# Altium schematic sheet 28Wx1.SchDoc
size A2; SheetNumber: 0; SheetTotal: 0; PageSetup: Record=PageOptions|CenterHorizontal=True|CenterVertical=True|PrintScale=0.52|XCorrection=1.00|YCorrection=1.00|PrintKind=0|BorderSize=5000000|LeftOffset=0|BottomOffset=0|Orientation=2|PaperLength=1000|PaperWidth=1000|Scale=100|PaperSource=7|PrintQuality=-4|MediaType=1|DitherType=10|PaperKind=A4|PrintScaleMode=1
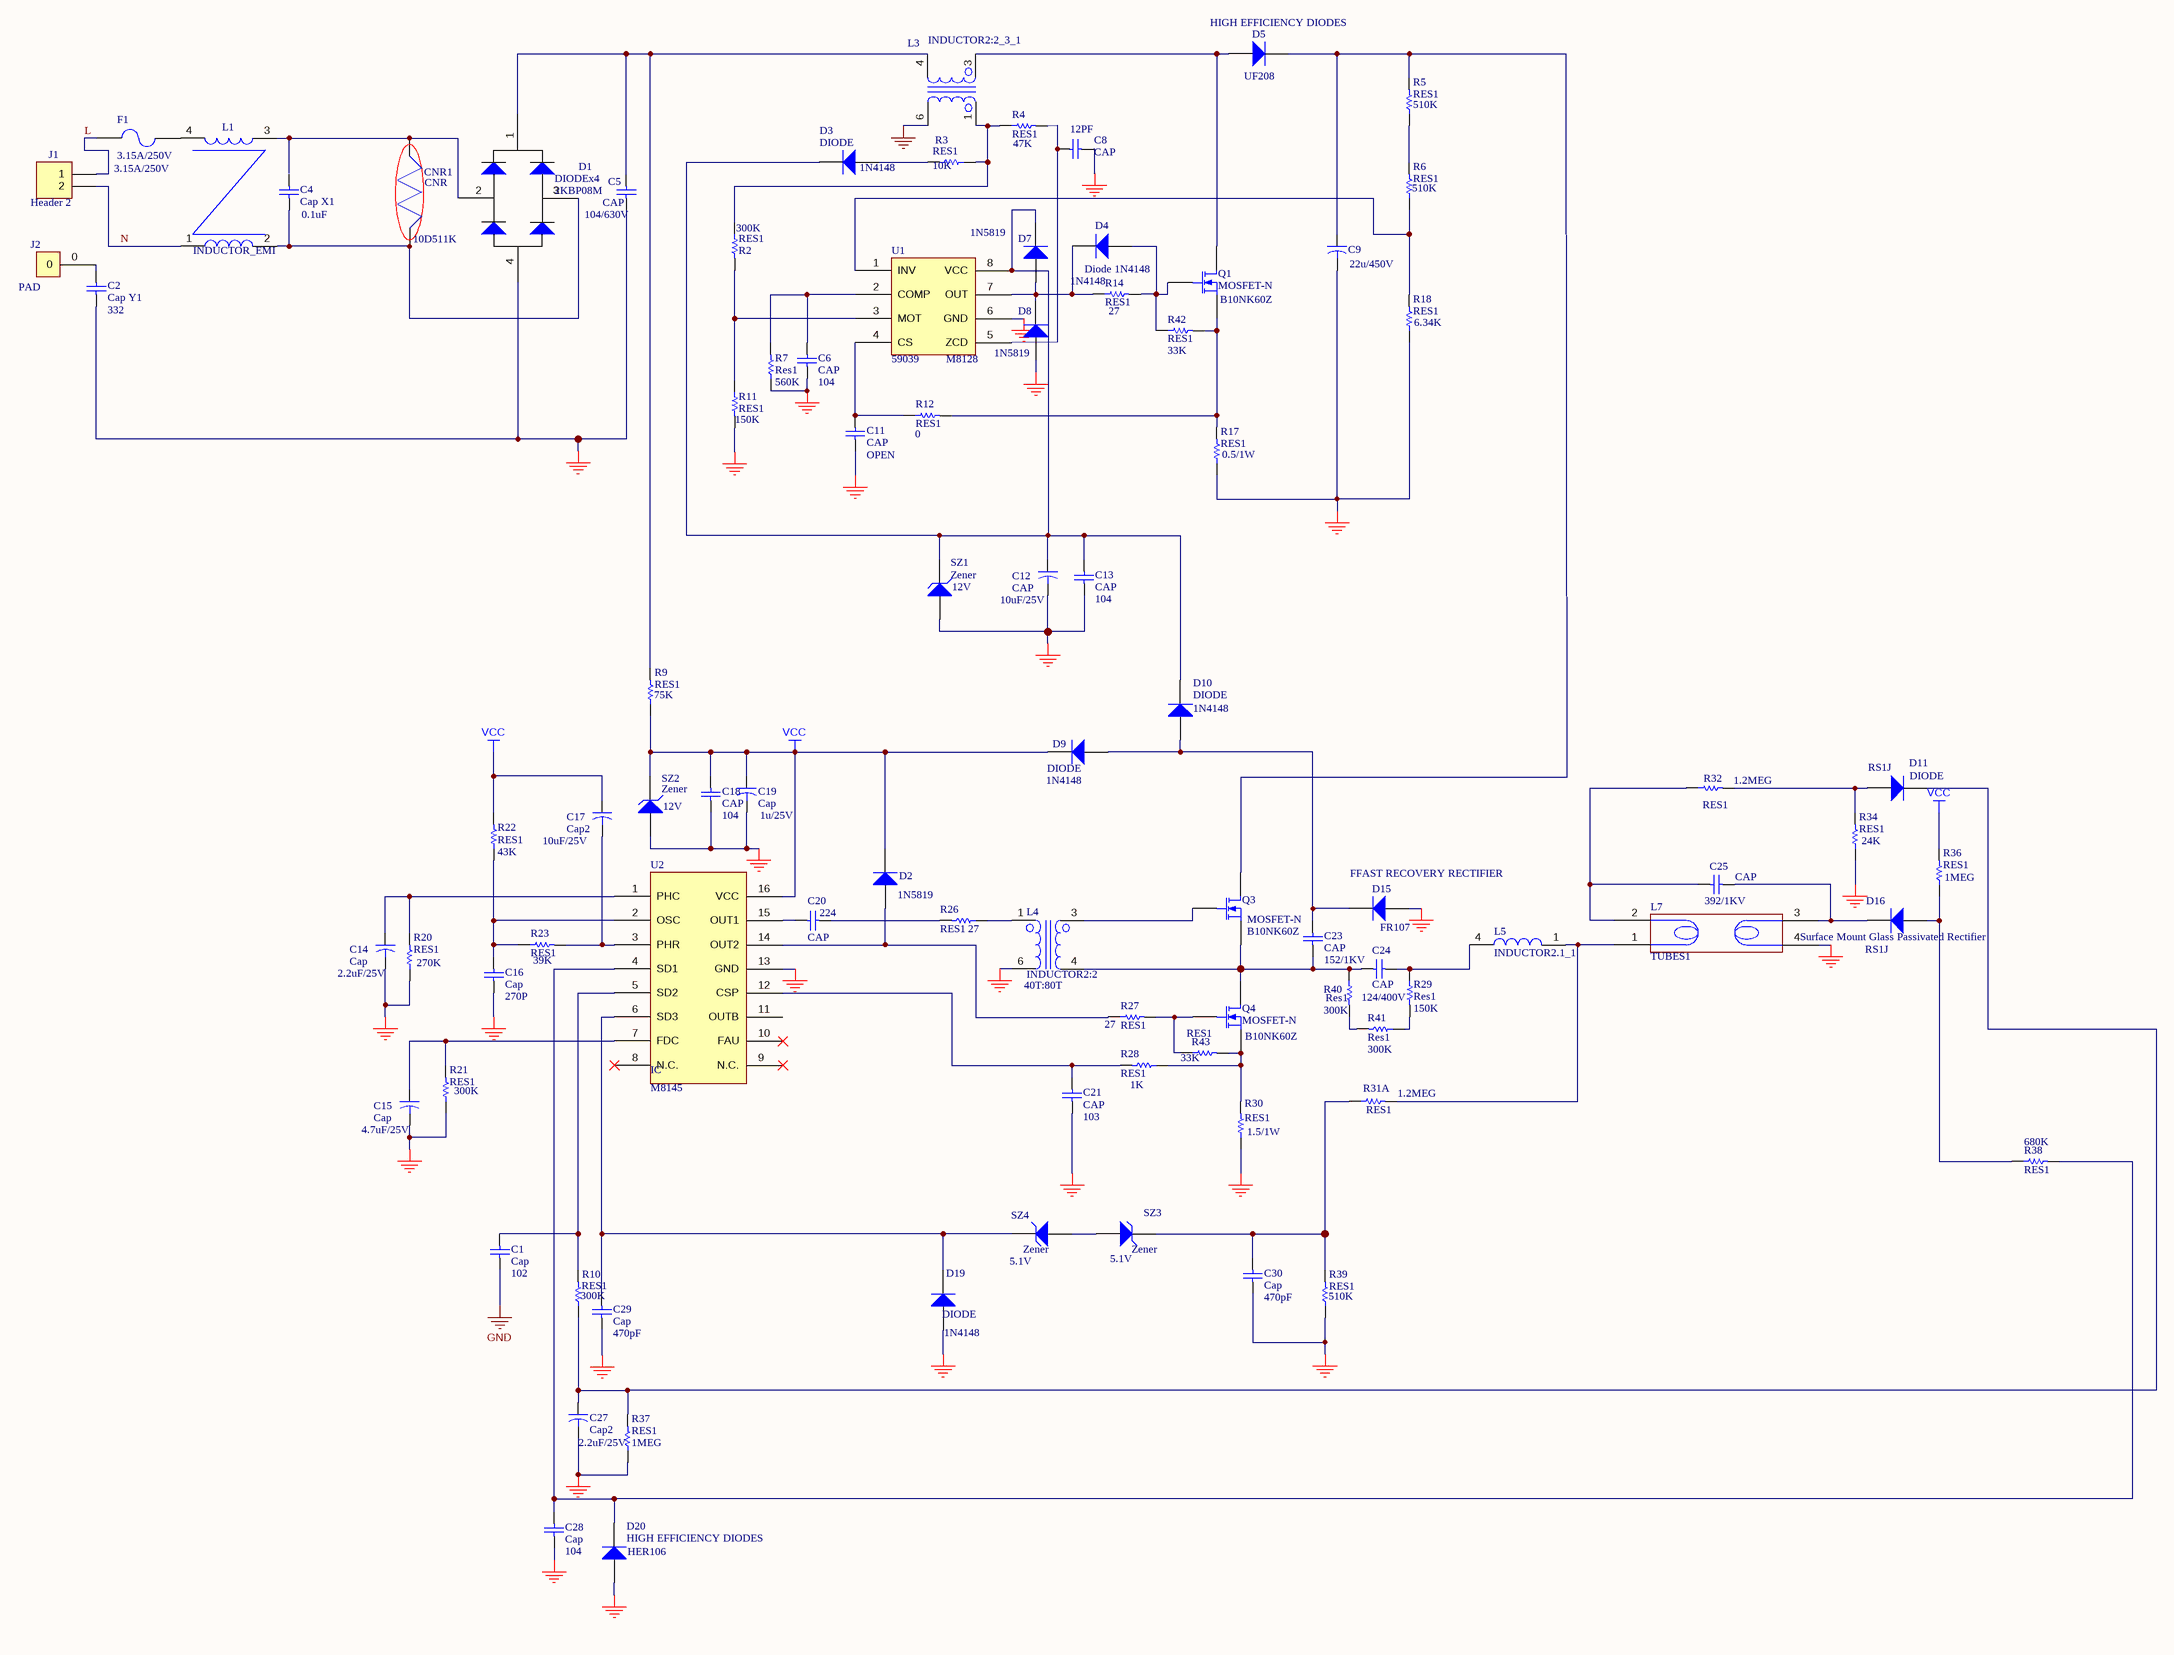
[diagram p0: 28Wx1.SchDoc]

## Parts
C1  Cap  value 102  [C0805A]
C2  Cap Y1  value 332  [RAD-0.3]
C4  Cap X1  value 0.1uF  [RAD0.6B]
C5  CAP  value 104/630V  [RAD0.6B]
C6  CAP  value 104  [RAD0.2B]
C8  CAP  value 12PF  [C0805A]
C9  value 22u/450V  [RB.3/.6A]  (hidden comment: Cap2)
C11  CAP  value OPEN  [C0805A]
C12  CAP  value 10uF/25V  [RB.2/.2]
C13  CAP  value 104  [RAD0.2B]
C14  Cap  value 2.2uF/25V  [RB.2/.2]
C15  Cap  value 4.7uF/25V  [RB.2/.2]
C16  Cap  value 270P  [C0805A]
C17  Cap2  value 10uF/25V  [RB.2/.2]
C18  CAP  value 104  [RAD0.2B]
C19  Cap  value 1u/25V  [RB.2/.2]
C20  CAP  value 224  [C0805A]
C21  CAP  value 103  [C0805A]
C23  CAP  value 152/1KV  [RAD-0.3]
C24  CAP  value 124/400V  [RAD0.6A]
C25  CAP  value 392/1KV  [RAD0.6A]
C27  Cap2  value 2.2uF/25V  [RB.2/.2]
C28  Cap  value 104  [C0805A]
C29  Cap  value 470pF  [C0805A]
C30  Cap  value 470pF  [C0805A]
CNR1  CNR  value 10D511K  [RAD-0.2]
D1  DIODEx4  value 2KBP08M  [SIP4C]
D2  value 1N5819  [DO-41]  (hidden comment: Diode 1N5819)
D3  DIODE  value 1N4148  [CD3216-1206A]
D4  Diode 1N4148  value 1N4148  [CD3216-1206A]
D5  HIGH EFFICIENCY DIODES  value UF208  [DIODE-0.4]
D7  value 1N5819  [CD4532-1812A]  (hidden comment: Diode 1N5819)
D8  value 1N5819  [CD4532-1812A]  (hidden comment: Diode 1N5819)
D9  DIODE  value 1N4148  [CD3216-1206A]
D10  DIODE  value 1N4148  [CD3216-1206A]
D11  DIODE  value RS1J  [CD4532-1810]
D15  FFAST RECOVERY RECTIFIER  value FR107  [DIODE-0.4]
D16  Surface Mount Glass Passivated Rectifier  value RS1J  [CD4532-1810]
D19  DIODE  value 1N4148  [CD3216-1206A]
D20  HIGH EFFICIENCY DIODES  value HER106  [DIODE-0.4]
F1  3.15A/250V  [FUSE0.6]
J1  Header 2  [IDC4-3.8mm]
J2  PAD  [GND1]
L1  INDUCTOR_EMI  [EE1414H]
L3  INDUCTOR2:2_3_1  [EE2520H]
L4  INDUCTOR2:2  value 40T:80T  [EE0808]
L5  INDUCTOR2.1_1  [EE2720H]
L7  TUBES1  [IDC8-3.8MM]
Q1  MOSFET-N  value B10NK60Z  [TO-220B]
Q3  MOSFET-N  value B10NK60Z  [TO-220B]
Q4  MOSFET-N  value B10NK60Z  [TO-220B]
R2  RES1  value 300K  [2012[0805]A]
R3  RES1  value 10K  [2012[0805]A]
R4  RES1  value 47K  [2012[0805]A]
R5  RES1  value 510K  [2012[0805]A]
R6  RES1  value 510K  [2012[0805]A]
R7  Res1  value 560K  [2012[0805]A]
R9  RES1  value 75K  [2012[0805]A]
R10  RES1  value 300K  [2012[0805]A]
R11  RES1  value 150K  [2012[0805]A]
R12  RES1  value 0  [2012[0805]A]
R14  RES1  value 27  [2012[0805]A]
R17  RES1  value 0.5/1W  [AXIAL-0.5]
R18  RES1  value 6.34K  [2012[0805]A]
R20  RES1  value 270K  [2012[0805]A]
R21  RES1  value 300K  [2012[0805]A]
R22  RES1  value 43K  [2012[0805]A]
R23  RES1  value 39K  [2012[0805]A]
R26  RES1  value 27  [2012[0805]A]
R27  RES1  value 27  [2012[0805]A]
R28  RES1  value 1K  [2012[0805]A]
R29  Res1  value 150K  [2012[0805]A]
R30  RES1  value 1.5/1W  [AXIAL-0.5]
R31A  RES1  value 1.2MEG  [2012[0805]A]
R32  RES1  value 1.2MEG  [2012[0805]A]
R34  RES1  value 24K  [2012[0805]A]
R36  RES1  value 1MEG  [2012[0805]A]
R37  RES1  value 1MEG  [2012[0805]A]
R38  RES1  value 680K  [2012[0805]A]
R39  RES1  value 510K  [2012[0805]A]
R40  Res1  value 300K  [2012[0805]A]
R41  Res1  value 300K  [2012[0805]A]
R42  RES1  value 33K  [2012[0805]A]
R43  RES1  value 33K  [2012[0805]A]
SZ1  Zener  value 12V  [CD3216-1206A]
SZ2  Zener  value 12V  [CD3216-1206A]
SZ3  Zener  value 5.1V  [CD3216-1206A]
SZ4  Zener  value 5.1V  [CD3216-1206A]
U1  59039  value M8128  [DIP-8]
U2  IC  value M8145  [SO-16]

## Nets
GND: C1.1 C2.1 C5.1 C6.1 C8.2 C9.2 C11.1 C12.2 C13.1 C14.2 C15.2 C16.1 C18.1 C19.2 C21.1 C27.2 C28.2 C29.1 C30.2 D1.4 D8.1(A) D15.1(A) D19.1(A) D20.1(A) L3.6 L4.6 L7.4(TR4) R7.1 R11.2 R17.1 R18.1 R20.1 R21.1 R30.1 R34.1 R37.1 R39.1 SZ1.1(A) SZ2.1(A) U1.6(GND) U2.13(GND)
VCC: C17.1 C18.2 C19.1 D2.2(K) D9.2(K) R9.1 R22.2 R36.2 SZ2.2(K) U2.16(VCC)
L: F1.1 J1.1
N: J1.2 L1.1(TR5)
NetC1_2: C1.2 R10.2 U2.5(SD2)
NetC2_2: C2.2 J2.0
NetC4_1: C4.1 CNR1.2 D1.3 L1.2(TR6)
NetC5_2: C5.2 D1.1 L3.4 R9.2
NetC6_2: C6.2 R7.2 U1.2(COMP)
NetC8_1: C8.1 R4.2 U1.5(ZCD)
NetC9_1: C9.1 D5.2(K) Q3.1(D) R5.2
NetC11_2: C11.2 R12.1 U1.4(CS)
NetC12_1: C12.1 C13.2 D3.2(K) D7.2(K) D10.2(K) SZ1.2(K) U1.8(VCC)
NetC14_1: C14.1 R20.2 U2.1(PHC)
NetC15_1: C15.1 R21.2 U2.7(FDC)
NetC16_2: C16.2 R22.1 R23.1 U2.2(OSC)
NetC17_2: C17.2 R23.2 U2.3(PHR)
NetC20_1: C20.1 R26.2
NetC20_2: C20.2 U2.15(OUT1)
NetC21_2: C21.2 R28.2 U2.12(CSP)
NetC23_1: C23.1 C24.2 L4.4 Q3.3(S) Q4.1(D) R40.1
NetC23_2: C23.2 D9.1(A) D10.1(A) D15.2(K)
NetC24_1: C24.1 L5.4 R29.1
NetC25_1: C25.1 L7.2(TR2) R32.1
NetC25_2: C25.2 D16.2(K) L7.3
NetC27_1: C27.1 D11.2(K) R10.1 R37.2
NetC28_1: C28.1 D20.2(K) R38.2 U2.4(SD1)
NetC29_2: C29.2 D19.2(K) SZ4.2(K) U2.6(SD3)
NetC30_1: C30.1 R31A.1 R39.2 SZ3.2(K)
NetCNR1_1: CNR1.1 D1.2 L1.3(TR5)
NetD2_1: D2.1(A) R27.1 U2.14(OUT2)
NetD3_1: D3.1(A) R3.2
NetD4_1: D4.1(A) Q1.2(G) R14.2 R42.1
NetD4_2: D4.2(K) D7.1(A) D8.2(K) R14.1 U1.7(OUT)
NetD5_1: D5.1(A) L3.3 Q1.1(D)
NetD11_1: D11.1(A) R32.2 R34.2
NetD16_1: D16.1(A) R36.1 R38.1
NetF1_2: F1.2 L1.4(TR6)
NetL3_1: L3.1 R2.1 R3.1 R4.1
NetL4_1: L4.1 R26.1
NetL4_3: L4.3 Q3.2(G)
NetL5_1: L5.1 L7.1(TR1) R31A.2
NetQ1_3: Q1.3(S) R12.2 R17.2 R42.2
NetQ4_2: Q4.2(G) R27.2 R43.1
NetQ4_3: Q4.3(S) R28.1 R30.2 R43.2
NetR2_2: R2.2 R11.1 U1.3(MOT)
NetR5_1: R5.1 R6.2
NetR6_1: R6.1 R18.2 U1.1(INV)
NetR29_2: R29.2 R41.1
NetR40_2: R40.2 R41.2
NetSZ3_1: SZ3.1(A) SZ4.1(A)

Not connected (* = marked no-connect by the designer): C4 2; U2 8(N.C.)* 9(N.C.)* 10(FAU)* 11(OUTB)

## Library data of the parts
C1 C16 C28-C30 = Cap: Ceramic Capacitor
C2 = CAP: Y Capacitor
C4 C5 = CAP: BOX Capacitor
C6 C8 C11 C20 C21 = CAP: Ceramic Capacitor
C9 C12 C14 C15 C17 C19 C27 = Cap2: Electrolytic Capacitor
C13 C18 C23 = CAP: MLCC Capacitor
C24 C25 = CAP: POLYPROPYLENE FILM Capacitor
CNR1 = CNR: Varistor
D1 = DIODEx4: Bridge Diode
D2 D7 D8 = Diode 1N4007: 1 Amp General Purpose Rectifier
D3 D9 D10 D19 = DIODE: Diode  75V,1A
D4 = Diode 1N4148: Diode  75V,1A
D5 = DIODE: Diode HIGH EFFICIENCY RECTIFIERS 600V, 3A
D11 D15 D16 = DIODE: Diode FAST RECOVERY RECTIFIER 700V,1A
D20 = DIODE: Diode HIGH EFFICIENCY RECTIFIERS 600V, 1A
F1 = FUSE2: Fuse
J1 = Header 2: Header, 2-Pin; Value: ºÝ¤l
L1 = INDUCTOR_EMI: EE19H Inductor; VALUE: 16mH
L3 = INDUCTOR2:2_3_1: TH07TS AXIS 0805
L4 = INDUCTOR2:2: EE08 Inductor
L5 = INDUCTOR2.1_1: T2-35A1JS LTE 0803
L7 = TUBES1: Header, 4-Pin; VALUE: LAMP
Q1 Q3 Q4 = MOSFET-N: Transistor, MOSFET  600V, 6A; PackageDocument: 1995/1996
R2-R6 R9-R12 R14 R18 R20-R23 R26-R28 R31A R32 R34 R36-R39 R42 R43 = RES1: Resistor 1/4W
R7 = Res1: Resistor
R17 R30 = RES1: Resistor 1W
R29 R40 R41 = Res1: Resistor 1/4W
SZ1 SZ2 = D Zener: Zener Diode
SZ3 SZ4 = D Zener: Zener Diode 1/4W
U1 = 59039: M8128
U2 = M8145_SOP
